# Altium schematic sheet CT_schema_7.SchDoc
size 278 x 170 mm
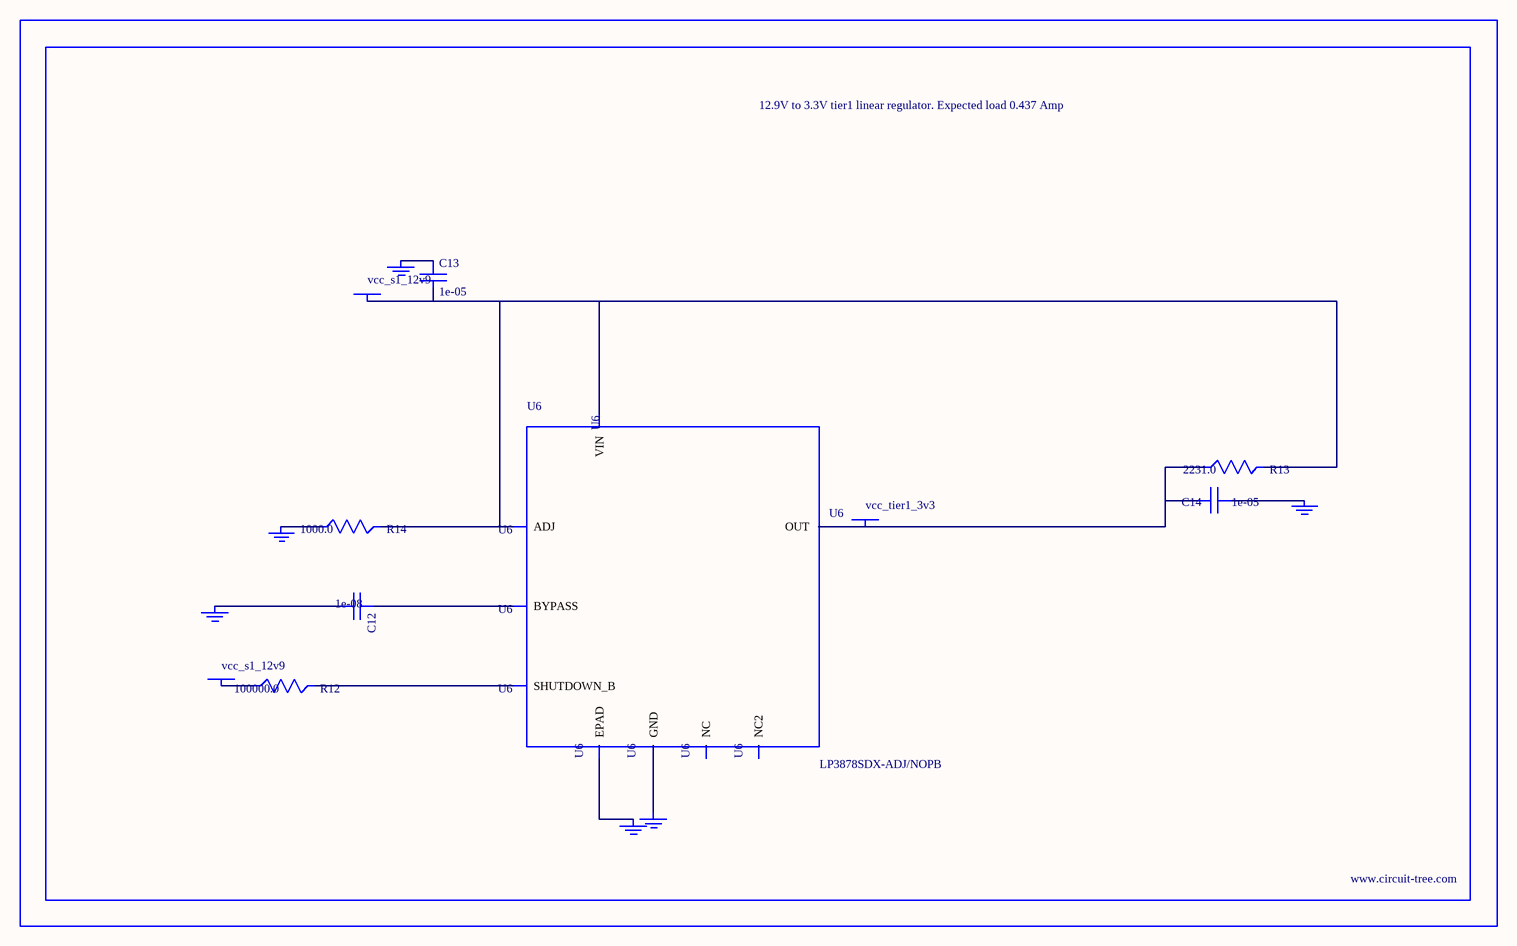
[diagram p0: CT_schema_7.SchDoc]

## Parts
BORDER6  (no value)
C12  1e-08  [C0402]
C13  1e-05  [C1210]
C14  1e-05  [C1210]
GND_INSTANCE_6_0  (no value)
GND_INSTANCE_6_1  (no value)
GND_INSTANCE_6_2  (no value)
GND_INSTANCE_6_3  (no value)
GND_INSTANCE_6_4  (no value)
GND_INSTANCE_6_5  (no value)
POWER_INSTANCE_6_0  vcc_s1_12v9
POWER_INSTANCE_6_1  vcc_s1_12v9
POWER_INSTANCE_6_2  vcc_tier1_3v3
R12  100000.0  [R0603]
R13  2231.0  [R0603]
R14  1000.0  [R0603]
U6  LP3878SDX-ADJ/NOPB  [WSON-8]

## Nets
NetC12_1: C12.1 U6.1(BYPASS)
NetC12_2: C12.2 GND_INSTANCE_6_0.0(GND)
NetC13_1: C13.1 GND_INSTANCE_6_1.0(GND)
NetC13_2: C13.2 POWER_INSTANCE_6_0.0(PWR) R13.2 R14.2 U6.4(VIN) U6.6(ADJ)
NetC14_1: C14.1 GND_INSTANCE_6_2.0(GND)
NetC14_2: C14.2 POWER_INSTANCE_6_2.0(PWR) R13.1 U6.5(OUT)
NetGND_INSTANCE_6_3_0: GND_INSTANCE_6_3.0(GND) R14.1
NetGND_INSTANCE_6_4_0: GND_INSTANCE_6_4.0(GND) U6.PAD(EPAD)
NetGND_INSTANCE_6_5_0: GND_INSTANCE_6_5.0(GND) U6.3(GND)
NetPOWER_INSTANCE_6_1_0: POWER_INSTANCE_6_1.0(PWR) R12.1
NetR12_2: R12.2 U6.8(SHUTDOWN_B)

Not connected (* = marked no-connect by the designer): U6 2(NC) 7(NC2)

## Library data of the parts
BORDER6 = BORDER_PAGE6
C12 = C0402C103K3RAC
C13 = C1210C106K5PACTU
C14 = GRM32DR61E106MA12L
GND_INSTANCE_6_0-GND_INSTANCE_6_5 = GND
POWER_INSTANCE_6_0-POWER_INSTANCE_6_2 = PWR
R12 = RC0603JR-07100KL
R13 = R13
R14 = RC0603JR-071KL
